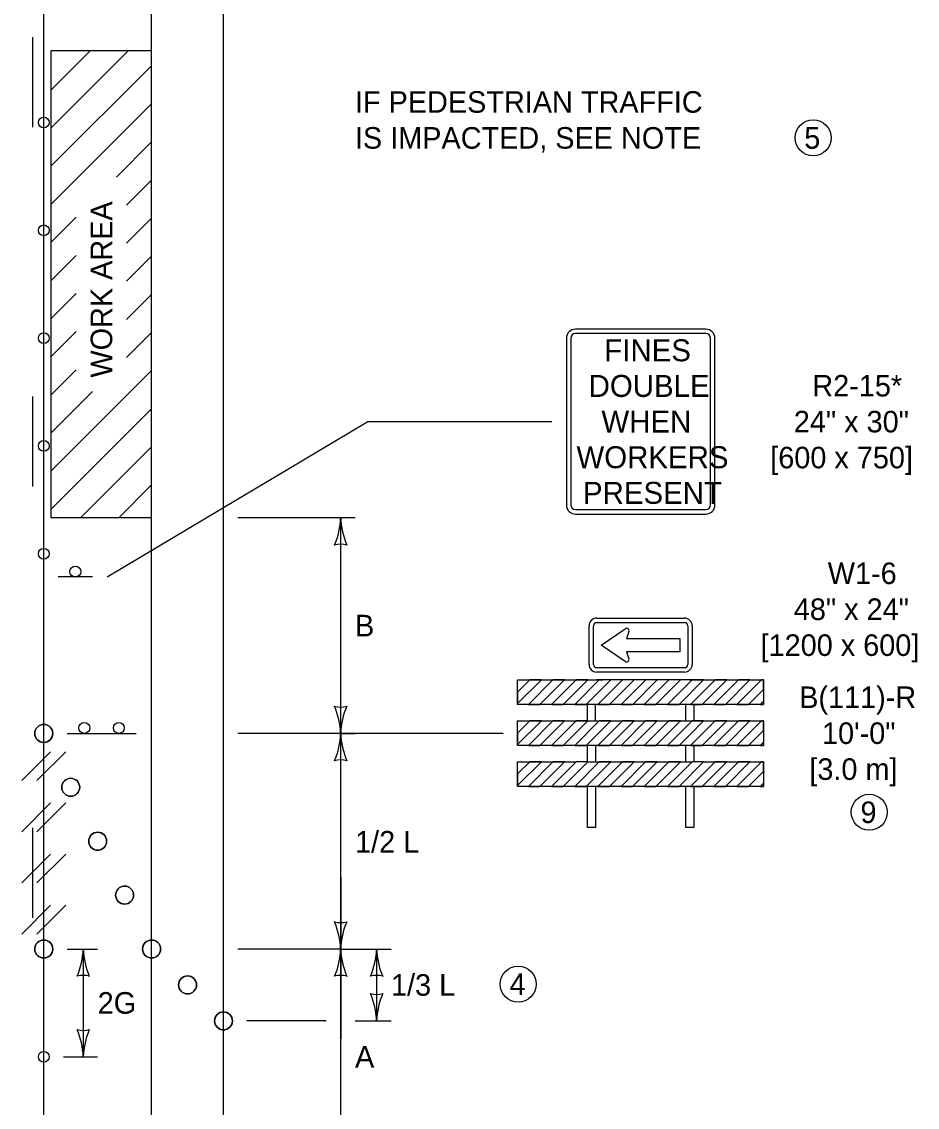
# Model space of a CAD drawing. Extents: x 49991.4 to 50021, y 49987.6 to 50011.4.
# Drawn here: x 50002.537 to 50005.028, y 50003.136 to 50006.157 of the extents above; entities that cross this region are included whole.
import ezdxf

# ---------------------------------------------------------------- set-up
doc = ezdxf.new("R2010")
doc.units = 0
for name, color, linetype in [('Level 1', 7, 'Continuous'), ('Level 2', 7, 'Continuous'), ('Level 3', 7, 'Continuous')]:
    doc.layers.add(name, color=color, linetype=linetype)

msp = doc.modelspace()

# ---------------------------------------------------------------- linework, layer by layer
at = {"layer": 'Level 1'}
for p, q in [((50002.5979, 50000.4631), (50002.5979, 50008.7736)), ((50002.8979, 50000.4631), (50002.8979, 50008.7736)), ((50003.0979, 50000.4631), (50003.0979, 50008.7736)), ((50002.5679, 50005.8631), (50002.5679, 50006.1131)), ((50002.6189, 50004.776), (50002.6189, 50006.076)), ((50002.6189, 50006.076), (50002.8979, 50006.076)), ((50002.6189, 50005.8611), (50002.8338, 50006.076)), ((50002.6189, 50005.9672), (50002.7277, 50006.076)), ((50002.6189, 50005.755), (50002.8979, 50006.034)), ((50002.6189, 50005.649), (50002.8979, 50005.9279)), ((50002.8002, 50005.7242), (50002.8979, 50005.8219)), ((50002.8284, 50005.6463), (50002.8979, 50005.7158)), ((50002.6189, 50005.5429), (50002.6884, 50005.6124)), ((50002.8284, 50005.5403), (50002.8979, 50005.6098)), ((50002.8284, 50005.5403), (50002.8284, 50005.5403)), ((50002.6189, 50005.4368), (50002.6884, 50005.5063)), ((50002.8284, 50005.4342), (50002.8979, 50005.5037)), ((50002.6189, 50005.3308), (50002.6884, 50005.4003)), ((50002.8284, 50005.3281), (50002.8979, 50005.3976)), ((50002.6189, 50005.2247), (50002.6884, 50005.2942)), ((50002.8284, 50005.2221), (50002.8979, 50005.2916)), ((50004.0517, 50005.2758), (50004.0517, 50004.8116)), ((50004.0641, 50005.2758), (50004.0641, 50004.8116)), ((50004.4397, 50005.3009), (50004.0768, 50005.3009)), ((50004.4397, 50005.2885), (50004.0768, 50005.2885)), ((50004.4524, 50004.8116), (50004.4524, 50005.2758)), ((50004.4648, 50004.8116), (50004.4648, 50005.2758)), ((50002.8284, 50005.2221), (50002.8284, 50005.2221)), ((50002.6189, 50005.1186), (50002.6884, 50005.1881)), ((50002.6189, 50004.9065), (50002.8979, 50005.1855)), ((50002.6189, 50005.0126), (50002.7337, 50005.1274)), ((50002.5679, 50004.8631), (50002.5679, 50005.1131)), ((50002.6189, 50004.8004), (50002.8979, 50005.0794)), ((50002.7005, 50004.776), (50002.8979, 50004.9734)), ((50002.8066, 50004.776), (50002.8979, 50004.8673)), ((50004.0768, 50004.7989), (50004.4397, 50004.7989)), ((50002.8979, 50004.776), (50002.6189, 50004.776)), ((50004.0768, 50004.7865), (50004.4397, 50004.7865)), ((50002.7339, 50004.6113), (50002.6379, 50004.6113)), ((50004.1357, 50004.4967), (50004.3808, 50004.4967)), ((50004.1147, 50004.3675), (50004.1147, 50004.4758)), ((50004.1271, 50004.3675), (50004.1271, 50004.4758)), ((50004.1357, 50004.4843), (50004.3808, 50004.4843)), ((50004.1487, 50004.4216), (50004.2152, 50004.4673)), ((50004.2257, 50004.4594), (50004.2194, 50004.4399)), ((50004.3893, 50004.4758), (50004.3893, 50004.3675)), ((50004.4017, 50004.4758), (50004.4017, 50004.3675)), ((50004.2194, 50004.4399), (50004.2296, 50004.4399)), ((50004.2296, 50004.4399), (50004.3677, 50004.4399)), ((50004.3677, 50004.4399), (50004.3677, 50004.4034)), ((50004.2152, 50004.3759), (50004.1487, 50004.4216)), ((50004.3677, 50004.4034), (50004.2194, 50004.4034)), ((50004.2194, 50004.4034), (50004.2257, 50004.3838)), ((50004.3808, 50004.3589), (50004.1357, 50004.3589)), ((50004.3808, 50004.3465), (50004.1357, 50004.3465)), ((50003.9162, 50004.2589), (50003.9821, 50004.3247)), ((50003.9162, 50004.2911), (50003.9498, 50004.3247)), ((50003.9498, 50004.3247), (50003.9162, 50004.2911)), ((50003.9162, 50004.2589), (50003.9821, 50004.3247)), ((50003.9459, 50004.2563), (50004.0143, 50004.3247)), ((50004.0143, 50004.3247), (50003.9459, 50004.2563)), ((50003.9781, 50004.2563), (50004.0465, 50004.3247)), ((50003.9781, 50004.2563), (50004.0465, 50004.3247)), ((50004.0104, 50004.2563), (50004.0788, 50004.3247)), ((50004.0788, 50004.3247), (50004.0104, 50004.2563)), ((50004.0426, 50004.2563), (50004.111, 50004.3247)), ((50004.0426, 50004.2563), (50004.111, 50004.3247)), ((50004.0749, 50004.2563), (50004.1433, 50004.3247)), ((50004.1071, 50004.2563), (50004.1755, 50004.3247)), ((50004.1214, 50004.3247), (50004.1528, 50004.3247)), ((50004.3808, 50004.3247), (50004.1357, 50004.3247)), ((50004.1396, 50004.2563), (50004.208, 50004.3247)), ((50004.1718, 50004.2563), (50004.2402, 50004.3247)), ((50004.204, 50004.2563), (50004.2724, 50004.3247)), ((50004.2362, 50004.2563), (50004.3046, 50004.3247)), ((50004.2684, 50004.2563), (50004.3368, 50004.3247)), ((50004.3006, 50004.2563), (50004.369, 50004.3247)), ((50004.3328, 50004.2563), (50004.4012, 50004.3247)), ((50004.4012, 50004.3247), (50004.3613, 50004.3247)), ((50004.365, 50004.2563), (50004.4334, 50004.3247)), ((50004.3973, 50004.2563), (50004.4657, 50004.3247)), ((50004.4657, 50004.3247), (50004.3973, 50004.2563)), ((50004.4295, 50004.2563), (50004.4979, 50004.3247)), ((50004.4295, 50004.2563), (50004.4979, 50004.3247)), ((50004.4617, 50004.2563), (50004.5301, 50004.3247)), ((50004.5301, 50004.3247), (50004.4617, 50004.2563)), ((50004.494, 50004.2563), (50004.5624, 50004.3247)), ((50004.494, 50004.2563), (50004.5624, 50004.3247)), ((50004.5262, 50004.2563), (50004.5946, 50004.3247)), ((50004.5946, 50004.3247), (50004.5262, 50004.2563)), ((50004.5585, 50004.2563), (50004.6002, 50004.2981)), ((50004.5585, 50004.2563), (50004.6002, 50004.2981)), ((50004.1328, 50004.2108), (50004.1328, 50004.2563)), ((50004.3836, 50004.2108), (50004.3836, 50004.2563)), ((50004.5907, 50004.2563), (50004.6002, 50004.2658)), ((50004.6002, 50004.2658), (50004.5907, 50004.2563)), ((50003.9162, 50004.1449), (50003.9821, 50004.2108)), ((50003.9162, 50004.1771), (50003.9498, 50004.2108)), ((50003.9498, 50004.2108), (50003.9162, 50004.1771)), ((50003.9162, 50004.1449), (50003.9821, 50004.2108)), ((50003.9459, 50004.1424), (50004.0143, 50004.2108)), ((50004.0143, 50004.2108), (50003.9459, 50004.1424)), ((50003.9781, 50004.1424), (50004.0465, 50004.2108)), ((50003.9781, 50004.1424), (50004.0465, 50004.2108)), ((50004.0104, 50004.1424), (50004.0788, 50004.2108)), ((50004.0788, 50004.2108), (50004.0104, 50004.1424)), ((50004.0426, 50004.1424), (50004.111, 50004.2108)), ((50004.0426, 50004.1424), (50004.111, 50004.2108)), ((50004.0749, 50004.1424), (50004.1433, 50004.2108)), ((50004.1071, 50004.1424), (50004.1755, 50004.2108)), ((50004.1393, 50004.1424), (50004.2077, 50004.2108)), ((50004.1716, 50004.1424), (50004.24, 50004.2108)), ((50004.2038, 50004.1424), (50004.2722, 50004.2108)), ((50004.2361, 50004.1424), (50004.3045, 50004.2108)), ((50004.2683, 50004.1424), (50004.3367, 50004.2108)), ((50004.3005, 50004.1424), (50004.3689, 50004.2108)), ((50004.3328, 50004.1424), (50004.395, 50004.2046)), ((50004.395, 50004.1724), (50004.4334, 50004.2108)), ((50004.395, 50004.2046), (50004.4012, 50004.2108)), ((50004.3973, 50004.1424), (50004.4657, 50004.2108)), ((50004.4657, 50004.2108), (50004.3973, 50004.1424)), ((50004.4295, 50004.1424), (50004.4979, 50004.2108)), ((50004.4295, 50004.1424), (50004.4979, 50004.2108)), ((50004.4617, 50004.1424), (50004.5301, 50004.2108)), ((50004.5301, 50004.2108), (50004.4617, 50004.1424)), ((50004.494, 50004.1424), (50004.5624, 50004.2108)), ((50004.494, 50004.1424), (50004.5624, 50004.2108)), ((50004.5262, 50004.1424), (50004.5946, 50004.2108)), ((50004.5946, 50004.2108), (50004.5262, 50004.1424)), ((50002.6628, 50004.176), (50002.7588, 50004.176)), ((50002.7588, 50004.176), (50002.8548, 50004.176)), ((50004.365, 50004.1424), (50004.395, 50004.1724)), ((50004.5585, 50004.1424), (50004.6002, 50004.1841)), ((50004.5585, 50004.1424), (50004.6002, 50004.1841)), ((50004.5907, 50004.1424), (50004.6002, 50004.1519)), ((50004.6002, 50004.1519), (50004.5907, 50004.1424)), ((50002.5366, 50004.0449), (50002.6166, 50004.1249)), ((50002.5791, 50004.0449), (50002.6591, 50004.1249)), ((50003.9162, 50004.0309), (50003.9821, 50004.0968)), ((50003.9162, 50004.0632), (50003.9498, 50004.0968)), ((50003.9498, 50004.0968), (50003.9162, 50004.0632)), ((50003.9162, 50004.0309), (50003.9821, 50004.0968)), ((50003.9459, 50004.0284), (50004.0143, 50004.0968)), ((50004.0143, 50004.0968), (50003.9459, 50004.0284)), ((50003.9781, 50004.0284), (50004.0465, 50004.0968)), ((50003.9781, 50004.0284), (50004.0465, 50004.0968)), ((50004.0104, 50004.0284), (50004.0788, 50004.0968)), ((50004.0788, 50004.0968), (50004.0104, 50004.0284)), ((50004.0426, 50004.0284), (50004.111, 50004.0968)), ((50004.0426, 50004.0284), (50004.111, 50004.0968)), ((50004.0749, 50004.0284), (50004.1433, 50004.0968)), ((50004.1433, 50004.0968), (50004.0749, 50004.0284)), ((50004.1071, 50004.0284), (50004.1755, 50004.0968)), ((50004.1071, 50004.0284), (50004.1755, 50004.0968)), ((50004.1393, 50004.0284), (50004.2077, 50004.0968)), ((50004.2077, 50004.0968), (50004.1393, 50004.0284)), ((50004.1716, 50004.0284), (50004.24, 50004.0968)), ((50004.1716, 50004.0284), (50004.24, 50004.0968)), ((50004.2038, 50004.0284), (50004.2722, 50004.0968)), ((50004.2722, 50004.0968), (50004.2038, 50004.0284)), ((50004.2361, 50004.0284), (50004.3045, 50004.0968)), ((50004.2361, 50004.0284), (50004.3045, 50004.0968)), ((50004.2683, 50004.0284), (50004.3367, 50004.0968)), ((50004.3367, 50004.0968), (50004.2683, 50004.0284)), ((50004.3005, 50004.0284), (50004.3689, 50004.0968)), ((50004.3005, 50004.0284), (50004.3689, 50004.0968)), ((50004.3328, 50004.0284), (50004.4012, 50004.0968)), ((50004.4012, 50004.0968), (50004.3328, 50004.0284)), ((50004.365, 50004.0284), (50004.4334, 50004.0968)), ((50004.365, 50004.0284), (50004.4334, 50004.0968)), ((50004.3973, 50004.0284), (50004.4657, 50004.0968)), ((50004.4657, 50004.0968), (50004.3973, 50004.0284)), ((50004.4295, 50004.0284), (50004.4979, 50004.0968)), ((50004.4295, 50004.0284), (50004.4979, 50004.0968)), ((50004.4617, 50004.0284), (50004.5301, 50004.0968)), ((50004.5301, 50004.0968), (50004.4617, 50004.0284)), ((50004.494, 50004.0284), (50004.5624, 50004.0968)), ((50004.494, 50004.0284), (50004.5624, 50004.0968)), ((50004.5262, 50004.0284), (50004.5946, 50004.0968)), ((50004.5946, 50004.0968), (50004.5262, 50004.0284)), ((50004.5585, 50004.0284), (50004.6002, 50004.0701)), ((50004.5585, 50004.0284), (50004.6002, 50004.0701)), ((50004.5907, 50004.0284), (50004.6002, 50004.0379)), ((50004.6002, 50004.0379), (50004.5907, 50004.0284)), ((50002.5366, 50003.9025), (50002.6166, 50003.9825)), ((50002.5791, 50003.9025), (50002.6591, 50003.9825)), ((50002.5679, 50003.6631), (50002.5679, 50003.9131)), ((50002.5366, 50003.7601), (50002.6166, 50003.8401)), ((50002.5791, 50003.7601), (50002.6591, 50003.8401)), ((50002.5366, 50003.6177), (50002.6166, 50003.6977)), ((50002.5791, 50003.6177), (50002.6591, 50003.6977))]:
    msp.add_line(p, q, dxfattribs=at)
for points in [[(50004.395, 50004.2563), (50003.9162, 50004.2563), (50003.9162, 50004.3247), (50004.1214, 50004.3247)], [(50003.9821, 50004.3247), (50003.9498, 50004.3247)], [(50004.0465, 50004.3247), (50004.0143, 50004.3247)], [(50004.1755, 50004.3247), (50004.1528, 50004.3247), (50004.1433, 50004.3247), (50004.0749, 50004.2563), (50004.1071, 50004.2563), (50004.1755, 50004.3247)], [(50004.111, 50004.3247), (50004.0788, 50004.3247)], [(50004.2402, 50004.3247), (50004.208, 50004.3247), (50004.1396, 50004.2563), (50004.1718, 50004.2563), (50004.2402, 50004.3247)], [(50004.3046, 50004.3247), (50004.2724, 50004.3247), (50004.204, 50004.2563), (50004.2362, 50004.2563), (50004.3046, 50004.3247)], [(50004.369, 50004.3247), (50004.3613, 50004.3247), (50004.3368, 50004.3247), (50004.2684, 50004.2563), (50004.3006, 50004.2563), (50004.369, 50004.3247)], [(50004.3328, 50004.2563), (50004.365, 50004.2563), (50004.4334, 50004.3247), (50004.4012, 50004.3247), (50004.3328, 50004.2563)], [(50004.395, 50004.3247), (50004.6002, 50004.3247), (50004.6002, 50004.2563), (50004.395, 50004.2563)], [(50004.4979, 50004.3247), (50004.4657, 50004.3247)], [(50004.5624, 50004.3247), (50004.5301, 50004.3247)], [(50004.6002, 50004.2981), (50004.6002, 50004.3247), (50004.5946, 50004.3247)], [(50003.9162, 50004.2911), (50003.9162, 50004.2589)], [(50003.9459, 50004.2563), (50003.9781, 50004.2563)], [(50004.0104, 50004.2563), (50004.0426, 50004.2563)], [(50004.11, 50004.2107), (50004.11, 50004.2563)], [(50004.3973, 50004.2563), (50004.4295, 50004.2563)], [(50004.4064, 50004.2563), (50004.4064, 50004.2108)], [(50004.4617, 50004.2563), (50004.494, 50004.2563)], [(50004.5262, 50004.2563), (50004.5585, 50004.2563)], [(50004.5907, 50004.2563), (50004.6002, 50004.2563), (50004.6002, 50004.2658)], [(50004.395, 50004.2108), (50004.6002, 50004.2108), (50004.6002, 50004.1424), (50003.9162, 50004.1424), (50003.9162, 50004.2108), (50004.395, 50004.2108)], [(50003.9821, 50004.2108), (50003.9498, 50004.2108)], [(50004.0465, 50004.2108), (50004.0143, 50004.2108)], [(50004.1755, 50004.2108), (50004.1433, 50004.2108), (50004.0749, 50004.1424), (50004.1071, 50004.1424), (50004.1755, 50004.2108)], [(50004.111, 50004.2108), (50004.0788, 50004.2108)], [(50004.24, 50004.2108), (50004.2077, 50004.2108), (50004.1393, 50004.1424), (50004.1716, 50004.1424), (50004.24, 50004.2108)], [(50004.3045, 50004.2108), (50004.2722, 50004.2108), (50004.2038, 50004.1424), (50004.2361, 50004.1424), (50004.3045, 50004.2108)], [(50004.3689, 50004.2108), (50004.3367, 50004.2108), (50004.2683, 50004.1424), (50004.3005, 50004.1424), (50004.3689, 50004.2108)], [(50004.3328, 50004.1424), (50004.365, 50004.1424), (50004.395, 50004.1724), (50004.4334, 50004.2108), (50004.4064, 50004.2108), (50004.4012, 50004.2108), (50004.395, 50004.2046), (50004.3328, 50004.1424)], [(50004.4979, 50004.2108), (50004.4657, 50004.2108)], [(50004.5624, 50004.2108), (50004.5301, 50004.2108)], [(50004.6002, 50004.1841), (50004.6002, 50004.2108), (50004.5946, 50004.2108)], [(50003.9162, 50004.1771), (50003.9162, 50004.1449)], [(50003.9459, 50004.1424), (50003.9781, 50004.1424)], [(50004.0104, 50004.1424), (50004.0426, 50004.1424)], [(50004.11, 50004.0968), (50004.11, 50004.1424)], [(50004.1328, 50004.1424), (50004.1328, 50004.0968)], [(50004.3836, 50004.0968), (50004.3836, 50004.1424)], [(50004.3973, 50004.1424), (50004.4295, 50004.1424)], [(50004.4064, 50004.1424), (50004.4064, 50004.0968)], [(50004.4617, 50004.1424), (50004.494, 50004.1424)], [(50004.5262, 50004.1424), (50004.5585, 50004.1424)], [(50004.5907, 50004.1424), (50004.6002, 50004.1424), (50004.6002, 50004.1519)], [(50004.4334, 50004.0968), (50004.6002, 50004.0968), (50004.6002, 50004.0284), (50003.9162, 50004.0284), (50003.9162, 50004.0968), (50004.0788, 50004.0968)], [(50003.9821, 50004.0968), (50003.9498, 50004.0968)], [(50004.0465, 50004.0968), (50004.0143, 50004.0968)], [(50004.111, 50004.0968), (50004.0788, 50004.0968)], [(50004.111, 50004.0968), (50004.4012, 50004.0968)], [(50004.1755, 50004.0968), (50004.1433, 50004.0968)], [(50004.24, 50004.0968), (50004.2077, 50004.0968)], [(50004.3045, 50004.0968), (50004.2722, 50004.0968)], [(50004.3689, 50004.0968), (50004.3367, 50004.0968)], [(50004.4334, 50004.0968), (50004.4012, 50004.0968)], [(50004.4979, 50004.0968), (50004.4657, 50004.0968)], [(50004.5624, 50004.0968), (50004.5301, 50004.0968)], [(50004.6002, 50004.0701), (50004.6002, 50004.0968), (50004.5946, 50004.0968)], [(50003.9162, 50004.0632), (50003.9162, 50004.0309)], [(50004.5907, 50004.0284), (50004.6002, 50004.0284), (50004.6002, 50004.0379)], [(50003.9459, 50004.0284), (50003.9781, 50004.0284)], [(50004.0104, 50004.0284), (50004.0426, 50004.0284)], [(50004.0749, 50004.0284), (50004.1071, 50004.0284)], [(50004.1328, 50004.0283), (50004.1328, 50003.9143), (50004.11, 50003.9143), (50004.11, 50004.0283)], [(50004.1393, 50004.0284), (50004.1716, 50004.0284)], [(50004.2038, 50004.0284), (50004.2361, 50004.0284)], [(50004.2683, 50004.0284), (50004.3005, 50004.0284)], [(50004.3328, 50004.0284), (50004.365, 50004.0284)], [(50004.4064, 50004.0283), (50004.4064, 50003.9143), (50004.3836, 50003.9143), (50004.3836, 50004.0283)], [(50004.3973, 50004.0284), (50004.4295, 50004.0284)], [(50004.4617, 50004.0284), (50004.494, 50004.0284)], [(50004.5262, 50004.0284), (50004.5585, 50004.0284)]]:
    msp.add_lwpolyline(points, dxfattribs=at)
for centre, radius in [((50002.5979, 50005.876), 0.015), ((50002.5979, 50005.576), 0.015), ((50002.5979, 50005.276), 0.015), ((50002.5979, 50004.976), 0.015), ((50002.5979, 50004.676), 0.015), ((50002.6858, 50004.6264), 0.0152), ((50002.5979, 50004.176), 0.025), ((50002.7108, 50004.1912), 0.0152), ((50002.8068, 50004.1912), 0.0152), ((50002.6729, 50004.026), 0.025), ((50002.7479, 50003.876), 0.025), ((50002.8229, 50003.726), 0.025), ((50002.5979, 50003.576), 0.025), ((50002.8979, 50003.576), 0.025), ((50002.9979, 50003.476), 0.025), ((50003.0979, 50003.376), 0.025), ((50002.5979, 50003.276), 0.015)]:
    msp.add_circle(centre, radius, dxfattribs=at)
for centre, radius, start, end in [((50004.0769, 50005.2758), 0.0251, 90, 180), ((50004.0769, 50005.2758), 0.0127, 90, 180), ((50004.4398, 50005.2758), 0.0251, 0, 90), ((50004.4398, 50005.2758), 0.0127, 0, 90), ((50004.0769, 50004.8116), 0.0251, 180, 270), ((50004.0769, 50004.8116), 0.0127, 180, 270), ((50004.4398, 50004.8116), 0.0127, 270, 0), ((50004.4398, 50004.8116), 0.0251, 270, 0), ((50004.1357, 50004.4758), 0.0209, 90, 180), ((50004.3808, 50004.4758), 0.0209, 0, 90), ((50004.1357, 50004.4758), 0.00855, 90, 180), ((50004.2191, 50004.4616), 0.00695, 342.0418, 124.5194), ((50004.3808, 50004.4758), 0.00855, 0, 90), ((50004.1357, 50004.3675), 0.0209, 180, 270), ((50004.1357, 50004.3675), 0.00855, 180, 270), ((50004.2191, 50004.3816), 0.00695, 235.4806, 17.9582), ((50004.3808, 50004.3675), 0.00855, 270, 0), ((50004.3808, 50004.3675), 0.0209, 270, 0), ((50002.5979, 50004.176), 0.025, 0, 180), ((50002.5979, 50004.176), 0.025, 180, 0), ((50002.6729, 50004.026), 0.025, 0, 180), ((50002.6729, 50004.026), 0.025, 180, 0), ((50002.7479, 50003.876), 0.025, 0, 180), ((50002.7479, 50003.876), 0.025, 180, 0), ((50002.8229, 50003.726), 0.025, 0, 180), ((50002.8229, 50003.726), 0.025, 180, 0), ((50002.5979, 50003.576), 0.025, 0, 180), ((50002.8979, 50003.576), 0.025, 0, 180), ((50002.5979, 50003.576), 0.025, 180, 0), ((50002.8979, 50003.576), 0.025, 180, 0), ((50002.9979, 50003.476), 0.025, 0, 180), ((50002.9979, 50003.476), 0.025, 180, 0), ((50003.0979, 50003.376), 0.025, 0, 180), ((50003.0979, 50003.376), 0.025, 180, 0)]:
    msp.add_arc(centre, radius, start, end, dxfattribs=at)
at = {"layer": 'Level 2'}
for centre, radius in [((50004.7383, 50005.8332), 0.0501), ((50004.8943, 50003.9565), 0.0501), ((50003.9176, 50003.4781), 0.05)]:
    msp.add_circle(centre, radius, dxfattribs=at)
at = {"layer": 'Level 3'}
for p, q in [((50002.7739, 50004.6113), (50003.499, 50005.0437)), ((50003.499, 50005.0437), (50004.0117, 50005.0437)), ((50003.4639, 50004.776), (50003.1379, 50004.776)), ((50003.4239, 50004.176), (50003.4239, 50004.776)), ((50003.8762, 50004.176), (50003.1379, 50004.176)), ((50003.4239, 50003.576), (50003.4239, 50004.176)), ((50003.4239, 50004.176), (50003.4639, 50004.176)), ((50003.4239, 50003.776), (50003.4239, 50003.326)), ((50002.6628, 50003.576), (50002.7479, 50003.576)), ((50002.7079, 50003.576), (50002.7079, 50003.276)), ((50003.4239, 50003.576), (50003.1379, 50003.576)), ((50003.4239, 50002.976), (50003.4239, 50003.576)), ((50003.4239, 50003.576), (50003.5639, 50003.576)), ((50003.5239, 50003.576), (50003.5239, 50003.376)), ((50003.3839, 50003.376), (50003.1628, 50003.376)), ((50003.4639, 50003.376), (50003.5639, 50003.376)), ((50002.6529, 50003.276), (50002.7479, 50003.276))]:
    msp.add_line(p, q, dxfattribs=at)
for centre, radius, start, end in [((50003.2017, 50004.7852), 0.2223, 337.456, 357.6395), ((50003.6566, 50004.7875), 0.233, 182.8273, 202.0772), ((50003.4239, 50004.6478), 0.0548, 72.1388, 107.8612), ((50003.4239, 50004.3042), 0.0548, 252.1388, 287.8612), ((50003.1911, 50004.1645), 0.233, 2.8273, 22.0772), ((50003.646, 50004.1668), 0.2223, 157.456, 177.6395), ((50003.2017, 50004.1852), 0.2223, 337.456, 357.6395), ((50003.6566, 50004.1875), 0.233, 182.8273, 202.0772), ((50003.4239, 50004.0478), 0.0548, 72.1388, 107.8612), ((50003.4239, 50003.7042), 0.0548, 252.1388, 287.8612), ((50003.1911, 50003.5645), 0.233, 2.8273, 22.0772), ((50003.646, 50003.5668), 0.2223, 157.456, 177.6395), ((50002.4857, 50003.5852), 0.2223, 337.456, 357.6395), ((50002.9406, 50003.5875), 0.233, 182.8273, 202.0772), ((50003.2017, 50003.5852), 0.2223, 337.456, 357.6395), ((50003.6566, 50003.5875), 0.233, 182.8273, 202.0772), ((50003.3017, 50003.5852), 0.2223, 337.456, 357.6395), ((50003.7566, 50003.5875), 0.233, 182.8273, 202.0772), ((50002.7079, 50003.4478), 0.0548, 72.1388, 107.8612), ((50003.4239, 50003.4478), 0.0548, 72.1388, 107.8612), ((50003.5239, 50003.4478), 0.0548, 72.1388, 107.8612), ((50003.5239, 50003.5042), 0.0548, 252.1388, 287.8612), ((50003.2911, 50003.3645), 0.233, 2.8273, 22.0772), ((50003.746, 50003.3668), 0.2223, 157.456, 177.6395), ((50002.7079, 50003.4042), 0.0548, 252.1388, 287.8612), ((50002.4751, 50003.2645), 0.233, 2.8273, 22.0772), ((50002.93, 50003.2668), 0.2223, 157.456, 177.6395)]:
    msp.add_arc(centre, radius, start, end, dxfattribs=at)

# ---------------------------------------------------------------- texts
at = {"layer": 'Level 1'}
for s, p in [('FINES', (50004.1572, 50005.2115)), ('DOUBLE', (50004.1137, 50005.1124)), ('WHEN', (50004.1492, 50005.0132)), ('WORKERS', (50004.0798, 50004.914)), ('PRESENT', (50004.0979, 50004.8148))]:
    msp.add_text(s, height=0.06119, dxfattribs=at).set_placement(p)
at = {"layer": 'Level 2'}
for s, p in [('IF PEDESTRIAN TRAFFIC', (50003.4635, 50005.9032)), ('IS IMPACTED, SEE NOTE', (50003.4635, 50005.8032)), ('5', (50004.7134, 50005.8032)), ('R2-15*', (50004.7359, 50005.1136)), ('24" x 30"', (50004.6844, 50005.0136)), ('[600 x 750]', (50004.6188, 50004.9136)), ('W1-6', (50004.7788, 50004.5916)), ('48" x 24"', (50004.6844, 50004.4916)), ('B', (50003.4639, 50004.446)), ('[1200 x 600]', (50004.5919, 50004.3916)), ('B(111)-R', (50004.6993, 50004.2466)), ('10\'-0"', (50004.7628, 50004.1466)), ('[3.0 m]', (50004.7276, 50004.0466)), ('9', (50004.8698, 50003.9265)), ('1/2 L', (50003.4639, 50003.8444)), ('1/3 L ', (50003.5639, 50003.446)), ('4', (50003.8936, 50003.4481)), ('2G', (50002.7479, 50003.396))]:
    msp.add_text(s, height=0.06, dxfattribs=at).set_placement(p)
for s, rotation, p in [('WORK AREA', 90, (50002.7884, 50005.1662)), ('A', 360, (50003.4639, 50003.246))]:
    msp.add_text(s, height=0.06, rotation=rotation, dxfattribs=at).set_placement(p)

doc.saveas('drawing.dxf')
